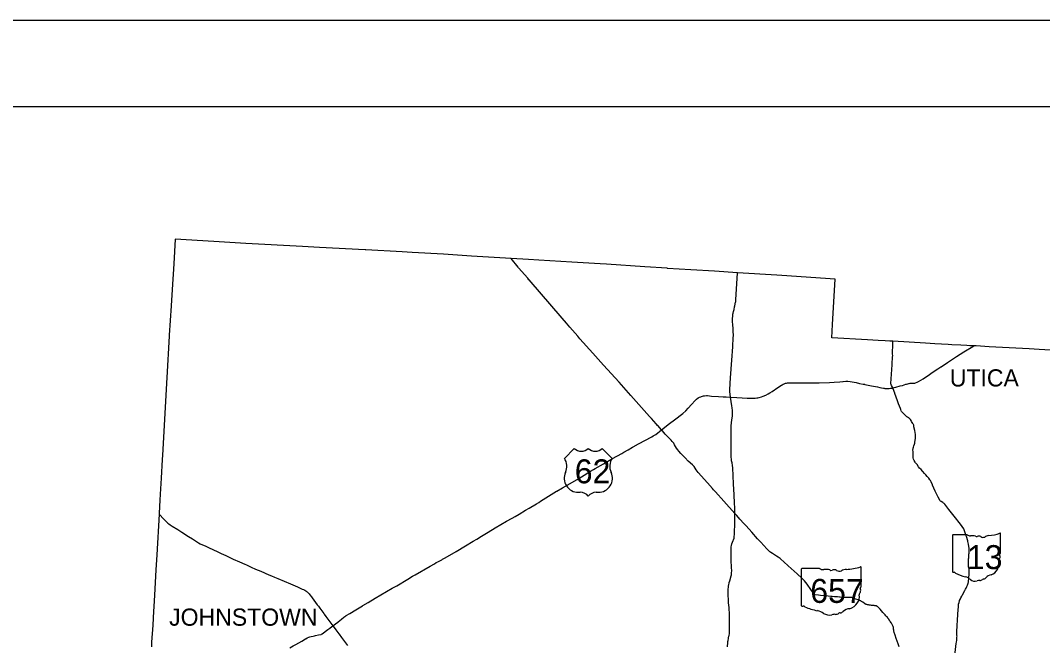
# Model space of a CAD drawing. Extents: x 1761803 to 2441803, y 509895 to 949895.
# Drawn here: x 1880534 to 1999264, y 877258 to 949895 of the extents above; entities that cross this region are included whole.
import ezdxf

# ---------------------------------------------------------------- set-up
doc = ezdxf.new("R2010")
doc.units = 0
for name, color, linetype in [('GM_X_County', 7, 'Continuous'), ('GM_X_County_Road', 7, 'Continuous'), ('GM_X_County_Road_Text', 7, 'Continuous'), ('GM_X_Minor_Lake', 7, 'Continuous'), ('GM_X_Minor_River_Text', 7, 'Continuous'), ('GM_X_Township_Road', 7, 'Continuous'), ('GM_X_Township_Road_Text', 7, 'Continuous'), ('GM_X_Township_Subdivision', 7, 'Continuous')]:
    doc.layers.add(name, color=color, linetype=linetype)

msp = doc.modelspace()

# ---------------------------------------------------------------- linework, layer by layer
at = {"layer": 'GM_X_County'}
msp.add_lwpolyline([(2000194, 911593), (1998869, 911653), (1997718, 911724), (1993053, 911984), (1991541, 912066), (1991301, 912077), (1990962, 912091), (1990797, 912097), (1990486, 912113), (1989752, 912152), (1988744, 912207), (1988298, 912233), (1986763, 912318), (1986195, 912348), (1985662, 912383), (1981878, 912613), (1981516, 912615), (1980999, 912647), (1980171, 912698), (1978931, 912776), (1974782, 913034), (1974872, 914557), (1974905, 915235), (1975185, 919849), (1968995, 920250), (1968380, 920282), (1963814, 920573), (1961147, 920745), (1958413, 920903), (1955710, 921085), (1955666, 921092), (1953054, 921262), (1948593, 921569), (1947878, 921617), (1944570, 921798), (1940743, 922038), (1939557, 922120), (1937526, 922240), (1933604, 922484), (1932924, 922522), (1929658, 922739), (1926023, 922933), (1924878, 923005), (1920661, 923248), (1920574, 923249), (1915254, 923516), (1913288, 923633), (1906704, 923993), (1903007, 924209), (1898513, 924466), (1898352, 921597), (1898155, 918638), (1898045, 916739), (1897825, 913330), (1897815, 913218), (1897557, 908421), (1897032, 899371), (1897004, 898896), (1896867, 896714), (1896762, 894856), (1896723, 894168), (1896641, 892645), (1896629, 892539), (1896376, 887790), (1896278, 886042), (1896113, 883102), (1895956, 880523), (1895947, 880445), (1895896, 879633), (1895772, 877650), (1895741, 877103)], dxfattribs=at)
at = {"layer": 'GM_X_County_Road_Text'}
for p, q in [((1944874, 900171), (1943714, 899011)), ((1949282, 899011), (1948122, 900171)), ((1945338, 895066), (1945570, 895066)), ((1947426, 895066), (1947658, 895066))]:
    msp.add_line(p, q, dxfattribs=at)
for centre, radius, start, end in [((1945686, 901000), 1160, 225.573, 314.427), ((1947310, 901000), 1160, 225.573, 314.427), ((1942383, 898079), 1624, 334.54712, 35.00093), ((1950613, 898079), 1624, 144.99907, 205.45288), ((1945320, 896691), 1624, 154.83192, 270.63826), ((1947676, 896691), 1624, 269.36174, 25.16808), ((1945570, 893906), 1160, 36.8699, 90), ((1947426, 893906), 1160, 90, 143.1301)]:
    msp.add_arc(centre, radius, start, end, dxfattribs=at)
at = {"layer": 'GM_X_Minor_Lake'}
for points in [[(1938340, 921235), (1937533, 922237)], [(1939596, 919773), (1939458, 919933), (1938398, 921163), (1938340, 921235)], [(1963496, 916636), (1963513, 916715), (1963605, 917142), (1963616, 917214), (1963623, 917411), (1963814, 920573)], [(1953611, 903881), (1952060, 905625), (1951435, 906327), (1950076, 907853), (1948275, 909845), (1947030, 911230), (1945501, 912914), (1945399, 913039), (1945262, 913191), (1944358, 914256), (1943952, 914717), (1943465, 915286), (1939613, 919753), (1939596, 919773)], [(1963278, 915606), (1963282, 915686), (1963287, 915754), (1963315, 915887), (1963359, 916073), (1963423, 916290), (1963496, 916636)], [(1963340, 913660), (1963330, 913828), (1963309, 914027), (1963280, 914603), (1963262, 914823), (1963253, 915015), (1963253, 915190), (1963257, 915302), (1963273, 915501), (1963278, 915606)], [(1962930, 907016), (1963007, 908357), (1963154, 910429), (1963269, 911986), (1963338, 913055), (1963345, 913258), (1963345, 913442), (1963342, 913635), (1963340, 913660)], [(1981851, 910828), (1981858, 910912), (1981838, 911144), (1981843, 911490), (1981846, 911651), (1981872, 911795), (1981882, 912208), (1981865, 912403), (1981871, 912566)], [(1981766, 909511), (1981777, 909699), (1981802, 910209), (1981828, 910554), (1981851, 910828)], [(1981749, 909247), (1981762, 909438), (1981766, 909511)], [(1981654, 907669), (1981652, 907674), (1981643, 907704), (1981641, 907736), (1981644, 907830), (1981665, 908131), (1981693, 908457)], [(1981693, 908457), (1981705, 908588), (1981725, 908872), (1981749, 909247)], [(1981852, 907180), (1981819, 907288), (1981724, 907493), (1981689, 907576), (1981654, 907669)], [(1982097, 906597), (1981894, 907084), (1981852, 907180)], [(1963019, 906123), (1963019, 906123), (1962930, 906797), (1962927, 906970), (1962930, 907016)], [(1963528, 892601), (1963526, 892833), (1963505, 893311), (1963498, 893778), (1963429, 894811), (1963400, 895374), (1963371, 896045), (1963272, 897908), (1963250, 898167), (1963191, 898475), (1963149, 898715), (1963116, 898909), (1963094, 899165), (1963086, 899336), (1963102, 899880), (1963104, 901015), (1963088, 902602), (1963095, 902755), (1963100, 902877), (1963114, 903065), (1963125, 903195), (1963201, 903708), (1963229, 903914), (1963241, 904183), (1963244, 904304), (1963229, 904552), (1963196, 904878), (1963158, 905111), (1963019, 906123)], [(1982545, 905358), (1982427, 905686), (1982112, 906561), (1982097, 906597)], [(1984524, 898487), (1984454, 898585), (1984363, 898743), (1984276, 898910), (1984238, 899054), (1984236, 899121), (1984220, 899612), (1984215, 899781), (1984209, 899987), (1984210, 900042), (1984216, 900108), (1984233, 900181), (1984283, 900325), (1984325, 900448), (1984391, 900676), (1984422, 900791), (1984435, 900872), (1984473, 901133), (1984493, 901304), (1984502, 901403), (1984513, 901562), (1984511, 901684), (1984502, 901790), (1984414, 902239), (1984330, 902662), (1984293, 902856), (1984270, 902935), (1984245, 903000), (1984207, 903054), (1984124, 903188), (1984059, 903300), (1983993, 903407), (1983921, 903532), (1983891, 903572), (1983849, 903613), (1983783, 903670), (1983707, 903719), (1983591, 903781), (1983493, 903853), (1983434, 903901), (1983298, 904033), (1983073, 904242), (1982943, 904381), (1982880, 904461), (1982845, 904516), (1982790, 904675), (1982751, 904789), (1982545, 905358)], [(1954540, 902838), (1954387, 903010), (1953821, 903644), (1953611, 903881)], [(1955006, 902313), (1954560, 902817), (1954540, 902838)], [(1957015, 899846), (1956884, 899997), (1956742, 900185), (1956513, 900578), (1956414, 900759), (1956344, 900854), (1956249, 900978), (1956131, 901109), (1955931, 901325), (1955785, 901482), (1955445, 901840), (1955103, 902224), (1955006, 902313)], [(1963528, 892601), (1962229, 894055), (1961269, 895123), (1961053, 895359), (1960909, 895515), (1960337, 896171), (1959245, 897364), (1959032, 897659), (1958795, 898055), (1958749, 898112), (1958709, 898158), (1958615, 898245), (1958109, 898671), (1957735, 899063), (1957263, 899571), (1957032, 899827), (1957015, 899846)], [(1986486, 895898), (1986475, 895923), (1986310, 896280), (1986237, 896420), (1986183, 896520), (1986047, 896703), (1985868, 896912), (1985708, 897087), (1985561, 897259), (1985344, 897466), (1985317, 897526), (1985151, 897704), (1984983, 897887), (1984866, 898024), (1984680, 898281), (1984553, 898446), (1984524, 898487)], [(1990580, 889429), (1990546, 889549), (1990467, 889797), (1990362, 890120), (1990206, 890596), (1990131, 890818), (1989717, 891353), (1988977, 892305), (1988373, 893080), (1987893, 893681), (1987836, 893754), (1987761, 893815), (1987673, 893874), (1987499, 893978), (1987396, 894052), (1987331, 894125), (1987274, 894220), (1987138, 894493), (1986804, 895187), (1986486, 895898)], [(1896641, 892536), (1897200, 891952), (1897643, 891497), (1897757, 891410), (1897911, 891297), (1898148, 891145), (1898807, 890733), (1899294, 890420), (1900041, 889949), (1900533, 889641), (1900757, 889500), (1900989, 889344), (1901226, 889196), (1901430, 889089), (1902072, 888798), (1902386, 888656), (1902948, 888385), (1903394, 888175), (1903861, 887959), (1904375, 887719), (1905260, 887308), (1905987, 886970), (1906589, 886714), (1906785, 886622), (1907336, 886370), (1907856, 886147), (1908448, 885897), (1909389, 885488), (1909682, 885360), (1910030, 885217), (1910432, 885046), (1911923, 884421), (1912725, 884067), (1913105, 883888), (1913266, 883826)], [(1963467, 890179), (1963468, 890229), (1963509, 891558), (1963529, 892443), (1963528, 892601)], [(1982609, 877114), (1982480, 877466), (1982263, 878091), (1982132, 878472), (1982024, 878794), (1982013, 878831), (1981999, 878879), (1981986, 878935), (1981980, 878974), (1981972, 879054), (1981967, 879154), (1981964, 879268), (1981958, 879323), (1981951, 879365), (1981942, 879405), (1981927, 879446), (1981908, 879491), (1981882, 879542), (1981844, 879612), (1981783, 879714), (1981700, 879846), (1981662, 879908), (1981601, 880000), (1981540, 880087), (1981469, 880196), (1981452, 880219), (1981388, 880317), (1981343, 880401), (1981306, 880456), (1981278, 880497), (1981259, 880524), (1981238, 880551), (1981210, 880585), (1981186, 880613), (1981147, 880654), (1981071, 880729), (1980965, 880835), (1980707, 881113), (1980542, 881298), (1980389, 881473), (1980323, 881546), (1980275, 881602), (1980237, 881639), (1980198, 881680), (1980162, 881715), (1980116, 881755), (1980080, 881789), (1980052, 881809), (1980027, 881828), (1980004, 881841), (1979972, 881855), (1979943, 881866), (1979917, 881874), (1979885, 881881), (1979840, 881888), (1979787, 881893), (1979700, 881901), (1979527, 881918), (1979386, 881931), (1979278, 881943), (1979210, 881951), (1979123, 881962), (1979036, 881976), (1978978, 881987), (1978926, 881998), (1978864, 882012), (1978823, 882024), (1978781, 882038), (1978753, 882048), (1978728, 882058), (1978699, 882073), (1978679, 882083), (1978658, 882095), (1978624, 882118), (1978569, 882157), (1978379, 882289), (1978325, 882327), (1978235, 882390), (1978206, 882408), (1978189, 882419), (1978168, 882430), (1978148, 882438), (1978121, 882450), (1978086, 882464), (1978033, 882484), (1977836, 882559), (1977569, 882662), (1977474, 882698), (1977395, 882729), (1977354, 882745), (1977292, 882768), (1977232, 882791), (1977171, 882812), (1977113, 882828), (1977092, 882831), (1977056, 882837), (1977026, 882840), (1976987, 882842), (1976926, 882843), (1976849, 882843), (1976740, 882845), (1976590, 882841), (1976503, 882841), (1976419, 882841), (1976309, 882840), (1976234, 882839), (1976176, 882841), (1976130, 882843), (1976053, 882848), (1975955, 882855), (1975740, 882875), (1975659, 882882), (1975433, 882902), (1975110, 882929), (1974814, 882953), (1974654, 882967), (1974360, 882994), (1973997, 883031), (1973471, 883087), (1973233, 883115), (1972860, 883158), (1972805, 883168), (1972755, 883190), (1972698, 883258), (1972523, 883505), (1972340, 883771), (1971913, 884374), (1971747, 884598), (1971612, 884770), (1971475, 884926), (1971306, 885092), (1970746, 885596), (1970077, 886206), (1969731, 886520), (1969202, 886997), (1968879, 887287), (1968779, 887369), (1968562, 887521), (1968377, 887647), (1967909, 887942), (1967712, 888064), (1967571, 888158), (1967453, 888259), (1967249, 888478), (1966549, 889255), (1966168, 889673), (1965478, 890440), (1964828, 891167), (1964564, 891455), (1964108, 891961), (1963761, 892359), (1963703, 892422), (1963528, 892601)], [(1963074, 888444), (1963073, 888484), (1963081, 888604), (1963098, 888724), (1963142, 888901), (1963189, 889068), (1963257, 889270), (1963426, 889752), (1963459, 889937), (1963467, 890179)], [(1990683, 887435), (1990684, 887485), (1990699, 887701), (1990707, 887862), (1990723, 888012), (1990720, 888246), (1990723, 888404), (1990720, 888580), (1990701, 888760), (1990660, 889040), (1990602, 889354), (1990580, 889429)], [(1962665, 877098), (1962695, 877619), (1962703, 877737), (1962727, 877848), (1962779, 878062), (1962797, 878155), (1962797, 878158), (1962834, 878349), (1962847, 878414), (1962885, 878662), (1962901, 878780), (1962917, 878966), (1962914, 879310), (1962914, 879489), (1962886, 880822), (1962864, 881668), (1962787, 882236), (1962744, 883452), (1962746, 883685), (1962785, 884170), (1962815, 884365), (1962847, 884510), (1962867, 884595), (1962922, 884785), (1963080, 885343), (1963113, 885476), (1963133, 885608), (1963142, 885665), (1963154, 885978), (1963148, 886272), (1963108, 887225), (1963099, 887602), (1963074, 888444)], [(1990642, 886595), (1990642, 886598), (1990642, 886671), (1990649, 886843), (1990671, 887358), (1990676, 887383)], [(1990676, 887383), (1990682, 887416), (1990683, 887435)], [(1990646, 886490), (1990645, 886499), (1990642, 886542), (1990642, 886595)], [(1990737, 885873), (1990746, 886119), (1990740, 886168), (1990729, 886213), (1990715, 886251), (1990699, 886295), (1990677, 886349), (1990663, 886400), (1990652, 886441), (1990646, 886490)], [(1990647, 884613), (1990650, 884627), (1990658, 884672), (1990671, 884764), (1990692, 885021), (1990729, 885679), (1990737, 885873)], [(1990546, 884259), (1990557, 884284), (1990596, 884404), (1990623, 884506), (1990638, 884557), (1990647, 884613)], [(1913266, 883826), (1913427, 883764), (1913582, 883687), (1913700, 883606), (1913769, 883555), (1913850, 883483), (1913911, 883423), (1914059, 883252), (1914149, 883148), (1914334, 882909), (1914407, 882810), (1914615, 882545), (1915018, 881996)], [(1989486, 881719), (1989496, 881830), (1989511, 881997), (1989515, 882053), (1989560, 882263), (1989584, 882355), (1989607, 882430), (1989628, 882491), (1989714, 882675), (1989788, 882817), (1989878, 882986), (1989972, 883152), (1990254, 883670), (1990314, 883797), (1990385, 883928), (1990478, 884106), (1990546, 884259)], [(1915018, 881996), (1915080, 881911), (1915142, 881842), (1915312, 881604), (1915775, 880967)], [(1989314, 878601), (1989307, 878705), (1989304, 878897), (1989336, 879538), (1989365, 880264), (1989463, 881466), (1989486, 881719)], [(1915775, 880967), (1915816, 880910), (1916008, 880653), (1916478, 880010), (1916811, 879546)], [(1916811, 879546), (1916957, 879367), (1917162, 879087), (1917164, 879084)], [(1917164, 879084), (1917499, 878634), (1917541, 878574)], [(1917541, 878574), (1917824, 878179), (1918172, 877736), (1918176, 877730)], [(1918176, 877730), (1918516, 877258)], [(1988979, 875438), (1989228, 877495), (1989254, 877666)], [(1989254, 877666), (1989287, 877882), (1989309, 878074), (1989323, 878224), (1989331, 878352), (1989324, 878442), (1989317, 878549), (1989314, 878601)]]:
    msp.add_lwpolyline(points, dxfattribs=at)
at = {"layer": 'GM_X_Minor_River_Text'}
for points in [[(1987488, 909664), (1988216, 910143), (1988821, 910544), (1989254, 910834), (1990126, 911370), (1991180, 911997), (1991301, 912077)], [(1986524, 909022), (1986692, 909140), (1987091, 909409), (1987449, 909638), (1987488, 909664)], [(1981852, 907180), (1981922, 907202), (1982034, 907231), (1982202, 907276), (1982739, 907422), (1982984, 907488), (1983383, 907616), (1983453, 907637), (1983613, 907681), (1983714, 907702), (1983773, 907715), (1983899, 907729), (1983994, 907734), (1984217, 907739), (1984412, 907765), (1984508, 907787), (1984689, 907847), (1984771, 907885), (1984849, 907928), (1985135, 908104), (1985378, 908267), (1986137, 908767), (1986452, 908971), (1986524, 909022)], [(1942848, 895206), (1943482, 895595), (1945185, 896563), (1946020, 897055), (1946570, 897401), (1946765, 897517), (1947092, 897713), (1947307, 897831), (1948255, 898377), (1949325, 898977), (1950409, 899587), (1950617, 899714), (1951115, 899993), (1951636, 900305), (1951725, 900355), (1952331, 900698), (1953861, 901520), (1954049, 901628), (1954332, 901798), (1955006, 902313), (1955946, 903058), (1956508, 903489), (1957459, 904234), (1957823, 904535), (1958106, 904836), (1958466, 905256), (1958895, 905748), (1959075, 905897), (1959253, 906028), (1959399, 906103), (1959564, 906177), (1959664, 906211), (1959762, 906240), (1959869, 906264), (1960009, 906292), (1960211, 906298), (1960337, 906297), (1960825, 906250), (1961604, 906189), (1962182, 906168), (1962509, 906162), (1963019, 906123), (1963742, 906078), (1964368, 906033), (1964942, 906012), (1965480, 905994), (1965879, 906016), (1966076, 906040), (1966178, 906054), (1966336, 906085), (1966622, 906167), (1966814, 906232), (1967105, 906353), (1967377, 906491), (1967577, 906613), (1967868, 906797), (1968511, 907226), (1968955, 907523), (1969028, 907566), (1969126, 907622), (1969183, 907649), (1969392, 907732), (1969530, 907761), (1969653, 907785), (1969789, 907800), (1970498, 907803), (1971199, 907793), (1972298, 907793), (1973319, 907801), (1974501, 907811), (1975039, 907844), (1975709, 907917), (1976068, 907952)], [(1976068, 907952), (1976094, 907954), (1976413, 907981), (1976630, 907984), (1976898, 907957), (1977605, 907814), (1977983, 907715), (1978439, 907626), (1978585, 907612), (1978630, 907603), (1979385, 907451), (1980094, 907310), (1980376, 907240), (1980567, 907202), (1980776, 907164), (1980827, 907155)], [(1980827, 907155), (1980868, 907148), (1980955, 907138), (1981032, 907130)], [(1981032, 907130), (1981036, 907130), (1981131, 907125), (1981289, 907137), (1981438, 907139), (1981598, 907152), (1981705, 907153), (1981852, 907180)], [(1920319, 881899), (1920918, 882258), (1921747, 882747), (1923730, 883911), (1924239, 884210), (1925529, 884975), (1926084, 885306), (1926387, 885487), (1928139, 886480), (1928618, 886769), (1928834, 886898), (1929033, 886991), (1929238, 887099), (1929476, 887233), (1929556, 887284), (1929873, 887462), (1931133, 888199), (1932237, 888864), (1933131, 889391), (1933547, 889637), (1934099, 889969), (1934865, 890428), (1935693, 890938), (1937012, 891723), (1937657, 892051), (1937999, 892266), (1938467, 892542), (1939218, 892992), (1939627, 893234), (1940473, 893728), (1940743, 893895), (1940960, 894017), (1942817, 895187), (1942848, 895206)], [(1918385, 880734), (1918777, 880989), (1918787, 880995)], [(1918787, 880995), (1919501, 881414), (1919889, 881645)], [(1919889, 881645), (1920279, 881875), (1920319, 881899)], [(1916811, 879546), (1917125, 879773), (1917410, 879991)], [(1917410, 879991), (1917671, 880190), (1917802, 880290), (1917823, 880307), (1917833, 880315)], [(1917833, 880315), (1918104, 880539), (1918206, 880618), (1918340, 880705)], [(1918340, 880705), (1918344, 880707), (1918385, 880734)], [(1915490, 878571), (1915524, 878588), (1915593, 878631), (1916237, 879107), (1916475, 879288)], [(1916475, 879288), (1916513, 879317), (1916811, 879546)], [(1911833, 876987), (1912220, 877211), (1912522, 877385), (1913218, 877770), (1913646, 878040), (1913666, 878050)], [(1913666, 878050), (1913845, 878143), (1914018, 878220), (1914132, 878259), (1914321, 878307), (1914547, 878361), (1914692, 878385), (1914821, 878413)], [(1914821, 878413), (1915145, 878486), (1915462, 878558), (1915490, 878571)]]:
    msp.add_lwpolyline(points, dxfattribs=at)
at = {"layer": 'GM_X_Township_Road'}
for p, q in [((1988812, 890070), (1988812, 885843)), ((1990497, 890142), (1988867, 890142)), ((1994380, 888036), (1994380, 890247)), ((1994380, 888037), (1994380, 888036)), ((1971242, 886144), (1971242, 881917)), ((1973349, 886217), (1971311, 886217)), ((1978203, 884111), (1978203, 886321)), ((1978202, 884111), (1978203, 884111))]:
    msp.add_line(p, q, dxfattribs=at)
for centre, radius, start, end in [((1988876, 890079), 64.5, 98.1301, 188.1301), ((1990886, 890633), 626, 231.61951, 271.11188), ((1991093, 887769), 2246, 80.48669, 94.98827), ((1991603, 890100), 181, 219.79206, 297.10237), ((1991868, 889612), 375, 54.46668, 119.14113), ((1992353, 890282), 452, 233.85621, 294.82819), ((1993150, 888851), 1188, 97.34618, 120.76885), ((1992397, 895904), 5905, 275.84447, 288.90645), ((1994319, 890256), 62, 351.86209, 97.738), ((1992728, 886830), 1477, 292.30889, 8.98584), ((1994602, 887111), 419, 136.8065, 186.92959), ((1994366, 887874), 95.9, 107.94398, 210.33697), ((1993756, 887594), 576, 340.03296, 23.64957), ((1994314, 888028), 66.3, 289.60381, 7.73413), ((1988876, 885834), 65.1, 171.95839, 258.30661), ((1988886, 886266), 497, 267.33899, 280.60386), ((1988988, 885599), 179, 29.74838, 93.27175), ((1991249, 889397), 4265, 240.41292, 257.1985), ((1989977, 883944), 1334, 47.18416, 75.83597), ((1991420, 885578), 847, 230.70037, 286.29184), ((1991910, 884117), 696, 85.69512, 111.20995), ((1991971, 885262), 451, 268.77702, 315.54927), ((1992380, 884852), 127, 65.75173, 132.64842), ((1992325, 885433), 477, 282.87319, 323.27711), ((1993350, 884656), 809, 94.40312, 142.57675)]:
    msp.add_arc(centre, radius, start, end, dxfattribs=at)
for centre, major_axis, start_param, end_param in [((1971322, 886153), (80.6, 0), 1.7126934, 3.2834897), ((1973835, 886707), (782, 0), 4.042523, 4.731795), ((1974094, 883844), (2808, 0), 1.4047578, 1.6578581), ((1974731, 886175), (226, 0), 3.8360951, 5.1854146), ((1975063, 885686), (469, 0), 0.950623, 2.079405), ((1975668, 886356), (564, 0), 4.0815608, 5.1457227), ((1976665, 884926), (1485, 0), 1.6990114, 2.1078141), ((1975723, 891979), (7382, 0), 4.8143942, 5.0423688), ((1978126, 886331), (77.5, 0), 6.1411519, 7.9890352), ((1978481, 883185), (524, 0), 2.3877238, 3.2625369), ((1978185, 883948), (120, 0), 1.8839779, 3.6710726), ((1977422, 883669), (720, 0), 5.9346948, 6.6959481), ((1978120, 884102), (82.9, 0), 5.05454, 6.4181714), ((1976137, 882904), (1846, 0), 5.1017525, 6.4400178), ((1971323, 881908), (81.4, 0), 3.00124, 4.5083009), ((1971335, 882341), (621, 0), 4.6659457, 4.8974612), ((1971462, 881674), (224, 0), 0.5192072, 1.6278991), ((1974288, 885471), (5331, 0), 4.1959971, 4.4889607), ((1972699, 880019), (1668, 0), 0.8235189, 1.3235874), ((1974503, 881653), (1058, 0), 4.0264811, 4.9967352), ((1975192, 881336), (564, 0), 4.6910439, 5.5073738), ((1975702, 880927), (159, 0), 1.1475842, 2.3151517), ((1975634, 881508), (597, 0), 4.9370686, 5.64225), ((1976915, 880731), (1011, 0), 1.6476453, 2.4884337), ((1975115, 880191), (870, 0), 1.495662, 1.9409797)]:
    msp.add_ellipse(centre, major_axis=major_axis, ratio=0.8, start_param=start_param, end_param=end_param, dxfattribs=at)
at = {"layer": 'GM_X_Township_Road_Text'}
msp.add_lwpolyline([(1761803, 509895), (2441803, 509895), (2441803, 949895), (1761803, 949895)], close=True, dxfattribs=at)
at = {"layer": 'GM_X_Township_Subdivision'}
msp.add_lwpolyline([(1791803, 939895), (2431803, 939895), (2431803, 519895), (1791803, 519895)], close=True, dxfattribs=at)

# ---------------------------------------------------------------- texts
at = {"layer": 'GM_X_County_Road'}
for s, p in [('UTICA', (1988490, 907360)), ('JOHNSTOWN', (1897804, 879561))]:
    msp.add_text(s, height=2000, rotation=0.00001, dxfattribs=at).set_placement(p)
at = {"layer": 'GM_X_County_Road_Text'}
msp.add_text('62', height=2784.4, dxfattribs=at).set_placement((1944922, 896111))
at = {"layer": 'GM_X_Township_Road'}
for s, p in [('13', (1990470, 886141)), ('657', (1972280, 882216))]:
    msp.add_text(s, height=2784.4, dxfattribs=at).set_placement(p)

doc.saveas('drawing.dxf')
